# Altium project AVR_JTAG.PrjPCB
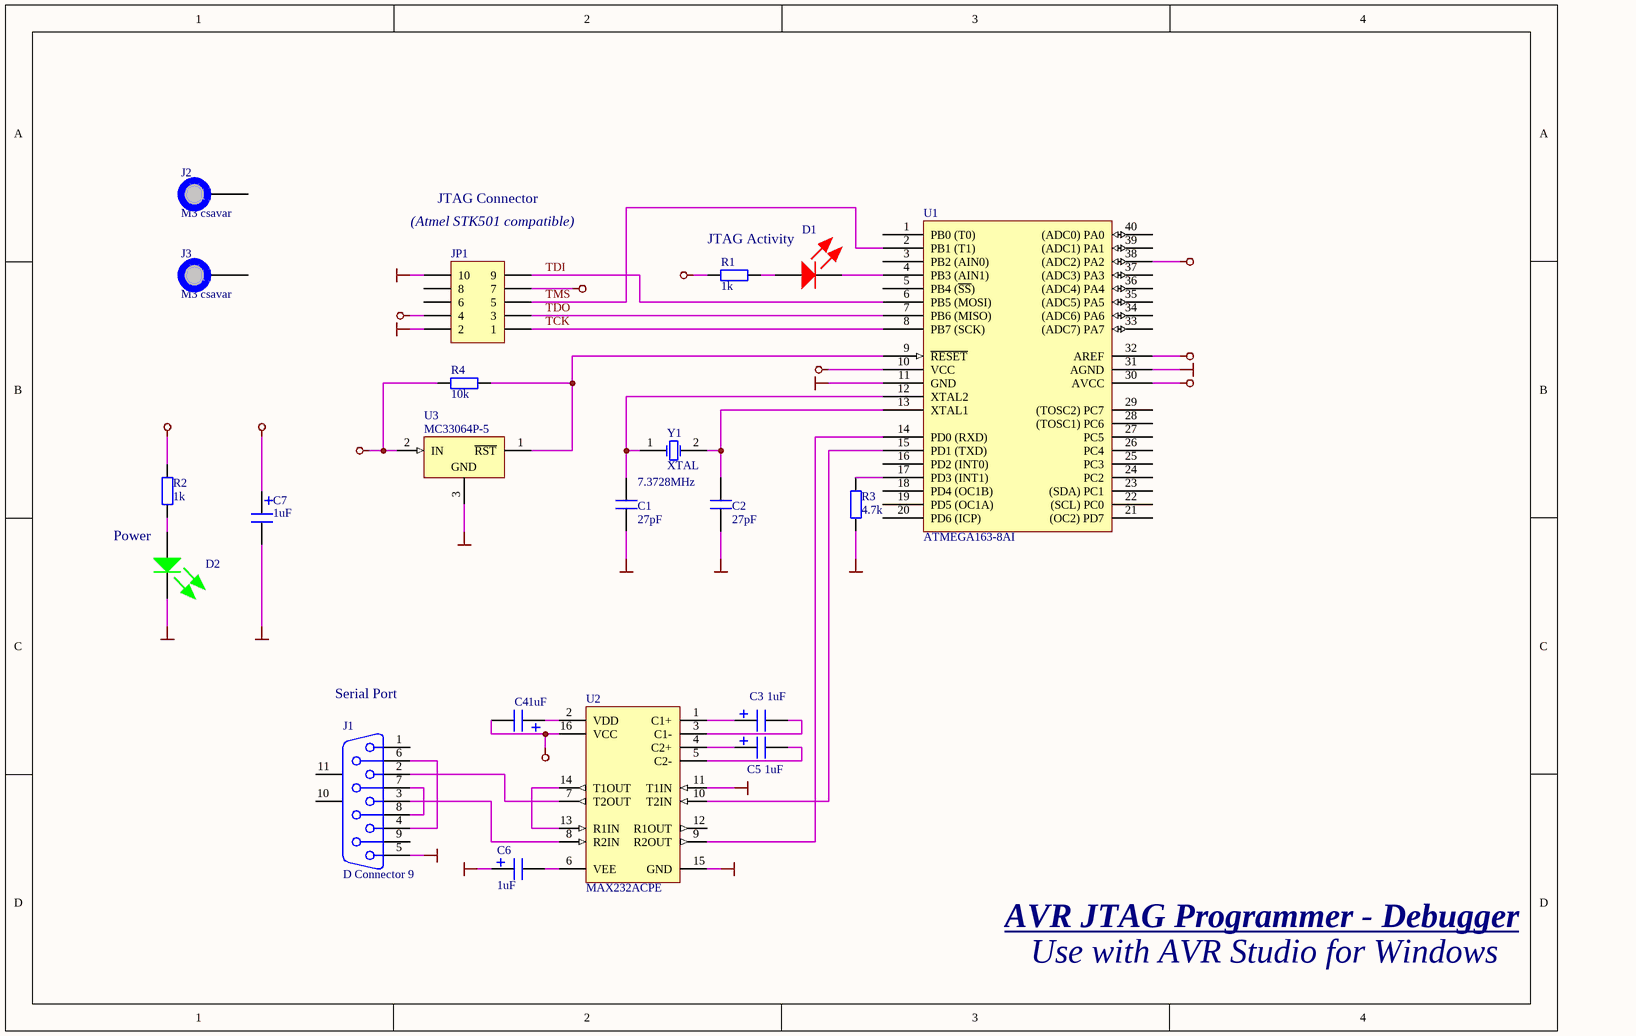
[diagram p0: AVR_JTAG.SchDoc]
1 sheet, 21 parts. Net scope: global (net labels, ports and power ports of the same name join across sheets).
Board files: AVR_JTAG.PcbDoc, AVR_JTAG_Kézi_fúrás.PcbDoc

## Sheet AVR_JTAG.SchDoc
size A4

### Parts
C1  value 27pF  [SMD1206]
C2  value 27pF  [SMD1206]
C3  value 1uF  [SMD1206 POL]
C4  value 1uF  [SMD1206 POL]
C5  value 1uF  [SMD1206 POL]
C6  value 1uF  [SMD1206 POL]
C7  value 1uF  [SMD1206 POL]
D1  (no value)  [LED 3MM]
D2  (no value)  [LED 3mm]
J1  D Connector 9  [DSUB9F90]
J2  M3 csavar  [M3 CSAVAR]
J3  M3 csavar  [M3 CSAVAR]
JP1  (no value)  [MLW10A]
R1  value 1k  [SMD1206]
R2  value 1k  [SMD1206]
R3  value 4.7k  [SMD1206]
R4  value 10k  [SMD1206]
U1  ATMEGA163-8AI  [DIP-40]
U2  MAX232ACPE  [DIP-16/X1.5]
U3  MC33064P-5  [BCY-W3]
Y1  XTAL  value 7.3728MHz  [XTAL]

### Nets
GND: C1.1 C2.1 C6.1 C7.2 D2.2 J1.5 JP1.2 JP1.10 R3.1 U1.11(GND) U1.31(AGND) U2.11(T1IN) U2.15(GND) U3.3(GND)
VCC: C4.2 C7.1 JP1.4 JP1.7 R1.1 R2.2 R4.2 U1.10(VCC) U1.30(AVCC) U1.32(AREF) U1.38((ADC2)_PA2) U2.16(VCC) U3.2(IN)
TCK: JP1.1 U1.8(PB7_(SCK))
TDI: JP1.9 U1.6(PB5_(MOSI))
TDO: JP1.3 U1.7(PB6_(MISO))
TMS: JP1.5 U1.2(PB1_(T1))
NetC1_2: C1.2 U1.12(XTAL2) Y1.1(OSC1)
NetC2_2: C2.2 U1.13(XTAL1) Y1.2(OSC2)
NetC3_1: C3.1 U2.1(C1+)
NetC3_2: C3.2 U2.3(C1-)
NetC4_1: C4.1 U2.2(VDD)
NetC5_1: C5.1 U2.4(C2+)
NetC5_2: C5.2 U2.5(C2-)
NetC6_2: C6.2 U2.6(VEE)
NetD1_1: D1.1 R1.2
NetD1_2: D1.2 U1.4(PB3_(AIN1))
NetD2_1: D2.1 R2.1
NetJ1_2: J1.2 U2.7(T2OUT)
NetJ1_3: J1.3 U2.8(R2IN)
NetJ1_4: J1.4 J1.6
NetJ1_7: J1.7 J1.8
NetR3_2: R3.2 U1.17(PD3_(INT1))
NetR4_1: R4.1 U1.9(~{RESET}) U3.1(~{RST})
NetU1_14: U1.14(PD0_(RXD)) U2.9(R2OUT)
NetU1_15: U1.15(PD1_(TXD)) U2.10(T2IN)
NetU2_13: U2.13(R1IN) U2.14(T1OUT)

Not connected (* = marked no-connect by the designer): J1 1 9 10(MH1) 11(MH2); J2 1; J3 1; JP1 6 8; U1 1(PB0_(T0)) 3(PB2_(AIN0)) 5(PB4_(~{SS})) 16(PD2_(INT0)) 18(PD4_(OC1B)) 19(PD5_(OC1A)) 20(PD6_(ICP)) 21((OC2)_PD7) 22((SCL)_PC0) 23((SDA)_PC1) 24(PC2) 25(PC3) 26(PC4) 27(PC5) 28((TOSC1)_PC6) 29((TOSC2)_PC7) 33((ADC7)_PA7) 34((ADC6)_PA6) 35((ADC5)_PA5) 36((ADC4)_PA4) 37((ADC3)_PA3) 39((ADC1)_PA1) 40((ADC0)_PA0); U2 12(R1OUT)

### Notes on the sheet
- (near JP1) (Atmel STK501 compatible)
- JTAG Connector
- JTAG Activity
- Power
- (near J1) Serial Port
- AVR JTAG Programmer - Debugger
- Use with AVR Studio for Windows

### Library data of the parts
C1 C2 = CAPSMD: Capacitor SMD1206; Bolt: RET
C3-C7 = CAPPOLSMD: Capacitor Polarity SMD1206; Bolt: RET
D1 = LED Piros: Piros Led 3mm; pin to pad: 2>3; Bolt: RET
D2 = LED Zöld: Zöld Led 3mm; pin to pad: 2>3; Bolt: RET
J1 = D Connector 9: Receptacle Assembly, 9 Position, Right Angle; Manufacturer: Generic Components; Positions: 9
J2 J3 = M3 CSAVAR: M3 csavar hely
JP1 = MLW10A: Header, 5-Pin, Dual row, Right Angle; Manufacturer: Generic Components; Class: Connector; Bolt: RET
R1-R4 = RES: Resistor SMD1206, 1% fémréteg; Bolt: RET
U1 = ATMEGA163-8AI: 8 bit microcontroller; pin to pad: 9>20; Manufacturer: Atmel; Class: 8-bit Microcontroller; Bolt: MSC
U2 = MAX232ACPE: +5V Powered, Multi-Channel RS-232 Driver/Receiver; Manufacturer: Maxim; Class: Communication; SubClass: Transceiver; Bolt: RET
U3 = MC33064P-5: Undervoltage Sensing Circuit; Manufacturer: ON Semiconductor; Class: Power Management; SubClass: Voltage Detector; Bolt: RET
Y1 = XTAL: Crystal Oscillator; Manufacturer: Generic Components; Bolt: RET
